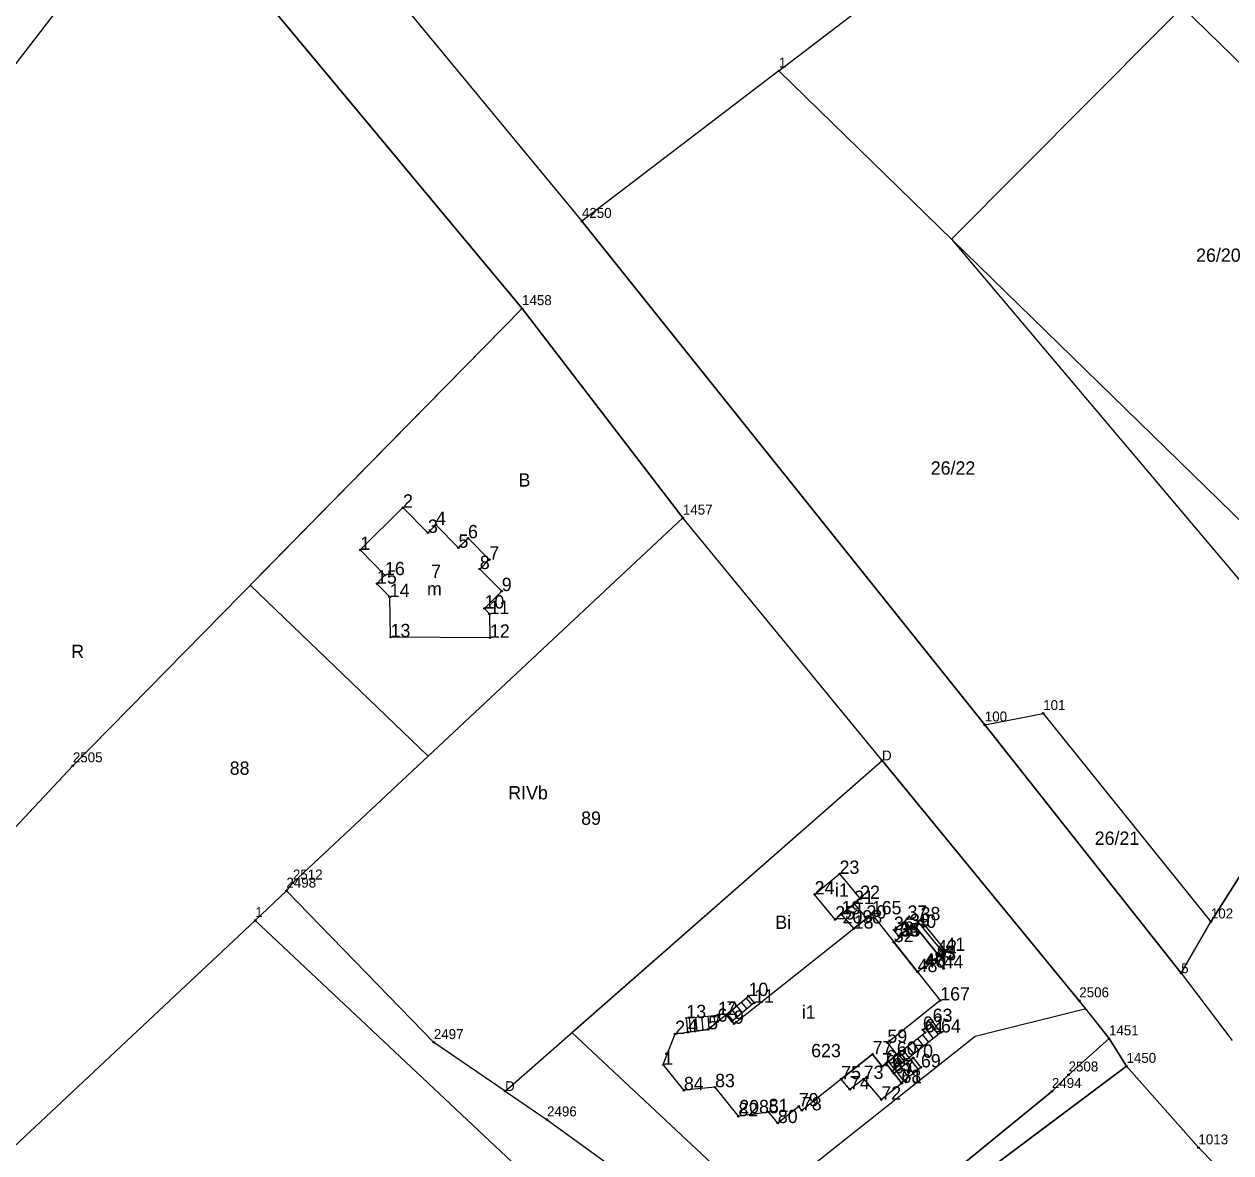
# Model space of a CAD drawing. Extents: x 7467189 to 7469366, y 5491487 to 5492734.
# Drawn here: x 7467609.4 to 7467745.4, y 5492014.5 to 5492141.7 of the extents above; entities that cross this region are included whole.
import ezdxf

# ---------------------------------------------------------------- set-up
doc = ezdxf.new("R2010")
doc.units = 0
for name, color, linetype in [('203-punkt graniczny', 7, 'Continuous'), ('203-punkt graniczny-Atr103', 7, 'Continuous'), ('209-oznaczenie konturu klasyfikacyjnego', 7, 'Continuous'), ('210-oznaczenie konturu użytku gruntowego', 7, 'Continuous'), ('211-numer działki ewidencyjnej', 7, 'Continuous'), ('217-kontur klasyfikacyjny', 7, 'Continuous'), ('218-kontur użytku gruntowego', 7, 'Continuous'), ('219-działka ewidencyjna', 7, 'Continuous'), ('312-budynek ewidencyjny', 7, 'Continuous'), ('312-oznaczenie budynku ewidencyjnego', 7, 'Continuous'), ('312-oznaczenie budynku ewidencyjnego-Atr117', 7, 'Continuous'), ('352-schody', 7, 'Continuous'), ('blok - nawis', 7, 'Continuous'), ('Punkt budynku', 7, 'Continuous'), ('Punkt budynku-Atr103', 7, 'Continuous'), ('Punkt budynku-Atr104', 7, 'Continuous')]:
    doc.layers.add(name, color=color, linetype=linetype)

# ---------------------------------------------------------------- blocks, each defined once
blk = doc.blocks.new('203')
blk.add_circle((0, 0), 0.09)
blk = doc.blocks.new('PUNKTBUD')
blk.add_circle((0, 0), 0.09)

msp = doc.modelspace()

# ---------------------------------------------------------------- linework, layer by layer
at = {"layer": '217-kontur klasyfikacyjny'}
for points in [[(7467768.85, 5492172.64), (7467713.9, 5492117.44)], [(7467665.5, 5492109.62), (7467624.48, 5492158.89)], [(7467651.98, 5492143.94), (7467672.25, 5492119.45)], [(7467672.25, 5492119.45), (7467717.66, 5492062.7)], [(7467713.9, 5492117.44), (7467758.45, 5492064.69)], [(7467634.87, 5492078.45), (7467665.5, 5492109.62)], [(7467683.63, 5492086.02), (7467654.93, 5492059.17)], [(7467706.08, 5492058.69), (7467683.63, 5492086.02)], [(7467654.93, 5492059.17), (7467634.87, 5492078.45)], [(7467743.14, 5492040.52), (7467758.45, 5492064.69)], [(7467717.66, 5492062.7), (7467739.8, 5492034.72)], [(7467671.13, 5492028.04), (7467706.08, 5492058.69)], [(7467739.8, 5492034.72), (7467743.14, 5492040.52)], [(7467728.94, 5492030.66), (7467716.58, 5492027.59)], [(7467729.04, 5492030.69), (7467728.94, 5492030.66)], [(7467731.66, 5492027.34), (7467729.04, 5492030.69)], [(7467692.22, 5492008.26), (7467671.13, 5492028.04)], [(7467716.58, 5492027.59), (7467692.22, 5492008.26)], [(7467727.1, 5492023.27), (7467731.66, 5492027.34)], [(7467733.63, 5492024.23), (7467703.66, 5492001.77)], [(7467741.74, 5492015.06), (7467733.63, 5492024.23)], [(7467725.22, 5492021.4), (7467727.1, 5492023.27)], [(7467711.49, 5492010.18), (7467725.22, 5492021.4)], [(7467745.33, 5492011.43), (7467741.74, 5492015.06)]]:
    msp.add_lwpolyline(points, dxfattribs=at)
at = {"layer": '218-kontur użytku gruntowego'}
for points in [[(7467665.5, 5492109.62), (7467624.48, 5492158.89)], [(7467651.98, 5492143.94), (7467672.25, 5492119.45)], [(7467672.25, 5492119.45), (7467717.66, 5492062.7)], [(7467665.5, 5492109.62), (7467634.87, 5492078.45)], [(7467683.63, 5492086.02), (7467665.5, 5492109.62)], [(7467654.93, 5492059.17), (7467683.63, 5492086.02)], [(7467706.08, 5492058.69), (7467683.63, 5492086.02)], [(7467634.87, 5492078.45), (7467654.93, 5492059.17)], [(7467743.14, 5492040.52), (7467758.45, 5492064.69)], [(7467717.66, 5492062.7), (7467739.8, 5492034.72)], [(7467671.13, 5492028.04), (7467706.08, 5492058.69)], [(7467728.31, 5492031.62), (7467706.08, 5492058.69)], [(7467739.8, 5492034.72), (7467743.14, 5492040.52)], [(7467729.04, 5492030.69), (7467728.31, 5492031.62)], [(7467728.94, 5492030.66), (7467716.58, 5492027.59)], [(7467729.04, 5492030.69), (7467728.94, 5492030.66)], [(7467731.66, 5492027.34), (7467729.04, 5492030.69)], [(7467692.22, 5492008.26), (7467671.13, 5492028.04)], [(7467716.58, 5492027.59), (7467692.22, 5492008.26)], [(7467731.66, 5492027.34), (7467727.1, 5492023.27)], [(7467733.63, 5492024.23), (7467731.66, 5492027.34)], [(7467711.14, 5492007.37), (7467733.63, 5492024.23)], [(7467741.74, 5492015.06), (7467733.63, 5492024.23)], [(7467727.1, 5492023.27), (7467725.22, 5492021.4)], [(7467725.22, 5492021.4), (7467711.49, 5492010.18)], [(7467745.33, 5492011.43), (7467741.74, 5492015.06)]]:
    msp.add_lwpolyline(points, dxfattribs=at)
at = {"layer": '219-działka ewidencyjna'}
for points in [[(7467624.48, 5492158.89), (7467665.5, 5492109.62)], [(7467694.46, 5492136.39), (7467724.09, 5492159.04)], [(7467724.09, 5492159.04), (7467782.84, 5492101.79)], [(7467613.61, 5492143.95), (7467605.35, 5492133.29)], [(7467651.98, 5492143.94), (7467672.25, 5492119.45)], [(7467694.46, 5492136.39), (7467672.25, 5492119.45)], [(7467694.46, 5492136.39), (7467762.1, 5492070.45)], [(7467717.66, 5492062.7), (7467672.25, 5492119.45)], [(7467614.87, 5492058.1), (7467665.5, 5492109.62)], [(7467665.5, 5492109.62), (7467683.63, 5492086.02)], [(7467639.67, 5492044.89), (7467683.63, 5492086.02)], [(7467706.08, 5492058.69), (7467683.63, 5492086.02)], [(7467762.1, 5492070.45), (7467743.14, 5492040.52)], [(7467717.66, 5492062.7), (7467724.24, 5492063.99)], [(7467724.24, 5492063.99), (7467743.14, 5492040.52)], [(7467739.8, 5492034.72), (7467717.66, 5492062.7)], [(7467598.43, 5492040.57), (7467614.87, 5492058.1)], [(7467663.59, 5492021.43), (7467706.08, 5492058.69)], [(7467706.08, 5492058.69), (7467728.31, 5492031.62)], [(7467638.94, 5492043.98), (7467639.67, 5492044.89)], [(7467635.43, 5492040.66), (7467638.94, 5492043.98)], [(7467638.94, 5492043.98), (7467655.56, 5492026.92)], [(7467605.73, 5492012.85), (7467635.43, 5492040.66)], [(7467635.43, 5492040.66), (7467685.71, 5491993.38)], [(7467739.8, 5492034.72), (7467743.14, 5492040.52)], [(7467739.8, 5492034.72), (7467745.55, 5492027.14)], [(7467728.31, 5492031.62), (7467731.66, 5492027.34)], [(7467663.59, 5492021.43), (7467655.56, 5492026.92)], [(7467727.1, 5492023.27), (7467731.66, 5492027.34)], [(7467731.66, 5492027.34), (7467733.63, 5492024.23)], [(7467703.66, 5492001.77), (7467733.63, 5492024.23)], [(7467733.63, 5492024.23), (7467741.74, 5492015.06)], [(7467725.22, 5492021.4), (7467727.1, 5492023.27)], [(7467663.59, 5492021.43), (7467668.32, 5492018.2)], [(7467711.49, 5492010.18), (7467725.22, 5492021.4)], [(7467668.32, 5492018.2), (7467694.32, 5491999.37)], [(7467741.74, 5492015.06), (7467745.33, 5492011.43)]]:
    msp.add_lwpolyline(points, dxfattribs=at)
at = {"layer": '312-budynek ewidencyjny'}
for points in [[(7467647.27, 5492082.42), (7467652.08, 5492087.18)], [(7467652.08, 5492087.18), (7467654.89, 5492084.34)], [(7467654.89, 5492084.34), (7467655.79, 5492085.23)], [(7467655.79, 5492085.23), (7467658.33, 5492082.66)], [(7467658.33, 5492082.66), (7467659.41, 5492083.73)], [(7467659.41, 5492083.73), (7467661.81, 5492081.32)], [(7467650.05, 5492079.57), (7467647.27, 5492082.42)], [(7467661.81, 5492081.32), (7467660.74, 5492080.26)], [(7467660.74, 5492080.26), (7467663.21, 5492077.78)], [(7467649.15, 5492078.61), (7467650.05, 5492079.57)], [(7467650.59, 5492077.11), (7467649.15, 5492078.61)], [(7467663.21, 5492077.78), (7467661.27, 5492075.81)], [(7467650.68, 5492072.58), (7467650.59, 5492077.11)], [(7467661.27, 5492075.81), (7467661.83, 5492075.2)], [(7467661.83, 5492075.2), (7467661.88, 5492072.52)], [(7467661.88, 5492072.52), (7467650.68, 5492072.58)], [(7467698.48, 5492043.59), (7467701.29, 5492045.91)], [(7467701.29, 5492045.91), (7467703.61, 5492043.09)], [(7467700.8, 5492040.77), (7467698.48, 5492043.59)], [(7467703.61, 5492043.09), (7467700.8, 5492040.77)], [(7467689.38, 5492029.02), (7467704.92, 5492041.35)], [(7467704.92, 5492041.35), (7467712.64, 5492031.64)], [(7467712.64, 5492031.64), (7467706.68, 5492026.87)], [(7467686.48, 5492028.39), (7467688.52, 5492030.05)], [(7467688.52, 5492030.05), (7467689.38, 5492029.02)], [(7467682.76, 5492027.87), (7467686.48, 5492028.39)], [(7467681.42, 5492024.41), (7467682.76, 5492027.87)], [(7467706.68, 5492026.87), (7467707.75, 5492025.52)], [(7467705.02, 5492025.58), (7467697.04, 5492019.26)], [(7467706.1, 5492024.21), (7467705.02, 5492025.58)], [(7467707.75, 5492025.52), (7467706.1, 5492024.21)], [(7467683.74, 5492021.53), (7467681.42, 5492024.41)], [(7467687.26, 5492021.87), (7467683.74, 5492021.53)], [(7467689.88, 5492018.6), (7467687.26, 5492021.87)], [(7467693.3, 5492019.06), (7467689.88, 5492018.6)], [(7467694.33, 5492017.83), (7467693.3, 5492019.06)], [(7467696.7, 5492019.71), (7467694.33, 5492017.83)], [(7467697.04, 5492019.26), (7467696.7, 5492019.71)]]:
    msp.add_lwpolyline(points, dxfattribs=at)
at = {"layer": '352-schody'}
for points in [[(7467708.09, 5492038.96), (7467707.98, 5492038.87), (7467707.42, 5492039.59), (7467708.95, 5492040.85), (7467710.42, 5492040.68), (7467713.23, 5492037.23), (7467713.01, 5492035.25), (7467712.21, 5492036.17), (7467712.29, 5492036.95), (7467709.95, 5492039.82), (7467709.23, 5492039.91)], [(7467708.09, 5492038.96), (7467707.98, 5492038.87), (7467707.42, 5492039.59), (7467708.95, 5492040.85), (7467710.42, 5492040.68), (7467713.23, 5492037.23), (7467713.01, 5492035.25), (7467712.21, 5492036.17), (7467712.29, 5492036.95), (7467709.95, 5492039.82), (7467709.23, 5492039.91)], [(7467707.4, 5492038.22), (7467708.18, 5492038.85), (7467708.09, 5492038.96), (7467709.23, 5492039.91), (7467709.95, 5492039.82), (7467712.29, 5492036.95), (7467712.21, 5492036.17), (7467712.08, 5492036.31), (7467710.96, 5492035.35), (7467710.87, 5492035.46), (7467710.09, 5492034.84)], [(7467707.4, 5492038.22), (7467708.18, 5492038.85), (7467708.09, 5492038.96), (7467709.23, 5492039.91), (7467709.95, 5492039.82), (7467712.29, 5492036.95), (7467712.21, 5492036.17), (7467712.08, 5492036.31), (7467710.96, 5492035.35), (7467710.87, 5492035.46), (7467710.09, 5492034.84)], [(7467688.52, 5492030.05), (7467691.02, 5492032.14), (7467691.66, 5492031.38), (7467689.16, 5492029.28)], [(7467688.52, 5492030.05), (7467691.02, 5492032.14), (7467691.66, 5492031.38), (7467689.16, 5492029.28)], [(7467684.19, 5492028.07), (7467684.02, 5492029.65), (7467687.57, 5492030), (7467687.53, 5492029.25), (7467686.48, 5492028.39)], [(7467684.19, 5492028.07), (7467684.02, 5492029.65), (7467687.57, 5492030), (7467687.53, 5492029.25), (7467686.48, 5492028.39)], [(7467707.23, 5492023.66), (7467706.53, 5492024.55), (7467707.75, 5492025.52), (7467710.92, 5492028.05), (7467710.68, 5492028.35), (7467711.78, 5492029.22), (7467712.72, 5492028.03)], [(7467707.23, 5492023.66), (7467706.53, 5492024.55), (7467707.75, 5492025.52), (7467710.92, 5492028.05), (7467710.68, 5492028.35), (7467711.78, 5492029.22), (7467712.72, 5492028.03)], [(7467708.27, 5492022.36), (7467707.41, 5492023.44), (7467709.59, 5492025.18), (7467710.46, 5492024.1)], [(7467708.27, 5492022.36), (7467707.41, 5492023.44), (7467709.59, 5492025.18), (7467710.46, 5492024.1)]]:
    msp.add_lwpolyline(points, close=True, dxfattribs=at)
for points in [[(7467709.92, 5492040.74), (7467713.18, 5492036.74)], [(7467689.68, 5492031.02), (7467690.32, 5492030.25)], [(7467690.21, 5492031.47), (7467690.85, 5492030.7)], [(7467690.75, 5492031.92), (7467691.39, 5492031.15)], [(7467684.52, 5492028.12), (7467684.37, 5492029.68)], [(7467685.22, 5492028.21), (7467685.07, 5492029.75)], [(7467685.91, 5492028.31), (7467685.76, 5492029.82)], [(7467686.6, 5492028.49), (7467686.46, 5492029.89)], [(7467687.25, 5492029.02), (7467687.16, 5492029.96)], [(7467688.6, 5492030.12), (7467689.25, 5492029.35)], [(7467689.14, 5492030.57), (7467689.78, 5492029.8)], [(7467711.89, 5492027.37), (7467710.94, 5492028.56)], [(7467712.43, 5492027.8), (7467711.49, 5492028.99)], [(7467710.24, 5492026.06), (7467709.54, 5492026.95)], [(7467710.79, 5492026.49), (7467710.08, 5492027.38)], [(7467711.34, 5492026.93), (7467710.63, 5492027.82)], [(7467708.6, 5492024.75), (7467707.89, 5492025.64)], [(7467709.15, 5492025.19), (7467708.44, 5492026.07)], [(7467709.7, 5492025.62), (7467708.99, 5492026.51)], [(7467707.5, 5492023.88), (7467706.8, 5492024.76)], [(7467708.05, 5492024.31), (7467707.35, 5492025.2)], [(7467709.09, 5492023.01), (7467708.23, 5492024.1)], [(7467709.64, 5492023.45), (7467708.78, 5492024.53)], [(7467710.19, 5492023.88), (7467709.33, 5492024.97)], [(7467708.54, 5492022.58), (7467707.69, 5492023.66)]]:
    msp.add_lwpolyline(points, dxfattribs=at)
at = {"layer": 'blok - nawis'}
for points in [[(7467702.89, 5492039.74), (7467701.51, 5492041.36), (7467702.92, 5492042.52), (7467704.32, 5492040.87)], [(7467701.47, 5492022.77), (7467705.02, 5492025.58), (7467706.1, 5492024.21), (7467706.53, 5492024.55), (7467707.23, 5492023.66), (7467707.41, 5492023.44), (7467708.27, 5492022.36), (7467708.32, 5492022.31), (7467706, 5492020.47), (7467704.01, 5492022.8), (7467702.45, 5492021.62)]]:
    msp.add_lwpolyline(points, close=True, dxfattribs=at)

# ---------------------------------------------------------------- block references
at = {"layer": '203-punkt graniczny'}
for p in [(7467694.46, 5492136.39), (7467672.25, 5492119.45), (7467665.5, 5492109.62), (7467683.63, 5492086.02), (7467724.24, 5492063.99), (7467717.66, 5492062.7), (7467614.87, 5492058.1), (7467706.08, 5492058.69), (7467639.67, 5492044.89), (7467638.94, 5492043.98), (7467635.43, 5492040.66), (7467743.14, 5492040.52), (7467739.8, 5492034.72), (7467728.31, 5492031.62), (7467655.56, 5492026.92), (7467731.66, 5492027.34), (7467733.63, 5492024.23), (7467727.1, 5492023.27), (7467663.59, 5492021.43), (7467725.22, 5492021.4), (7467668.32, 5492018.2), (7467741.74, 5492015.06)]:
    msp.add_blockref('203', p, dxfattribs=at)
at = {"layer": 'Punkt budynku'}
for p in [(7467652.08, 5492087.18), (7467655.79, 5492085.23), (7467654.89, 5492084.34), (7467658.33, 5492082.66), (7467659.41, 5492083.73), (7467647.27, 5492082.42), (7467661.81, 5492081.32), (7467660.74, 5492080.26), (7467649.15, 5492078.61), (7467650.05, 5492079.57), (7467650.59, 5492077.11), (7467663.21, 5492077.78), (7467661.27, 5492075.81), (7467661.83, 5492075.2), (7467650.68, 5492072.58), (7467661.88, 5492072.52), (7467701.29, 5492045.91), (7467698.48, 5492043.59), (7467703.61, 5492043.09), (7467702.92, 5492042.52), (7467700.8, 5492040.77), (7467701.51, 5492041.36), (7467704.32, 5492040.87), (7467704.92, 5492041.35), (7467708.95, 5492040.85), (7467710.42, 5492040.68), (7467702.89, 5492039.74), (7467707.42, 5492039.59), (7467708.09, 5492038.96), (7467709.23, 5492039.91), (7467709.95, 5492039.82), (7467707.4, 5492038.22), (7467707.98, 5492038.87), (7467708.18, 5492038.85), (7467712.08, 5492036.31), (7467712.29, 5492036.95), (7467713.23, 5492037.23), (7467710.87, 5492035.46), (7467710.96, 5492035.35), (7467712.21, 5492036.17), (7467713.01, 5492035.25), (7467710.09, 5492034.84), (7467691.02, 5492032.14), (7467691.66, 5492031.38), (7467712.64, 5492031.64), (7467684.02, 5492029.65), (7467687.57, 5492030), (7467688.52, 5492030.05), (7467684.19, 5492028.07), (7467686.48, 5492028.39), (7467687.53, 5492029.25), (7467689.16, 5492029.28), (7467689.38, 5492029.02), (7467710.68, 5492028.35), (7467711.78, 5492029.22), (7467682.76, 5492027.87), (7467706.68, 5492026.87), (7467710.92, 5492028.05), (7467712.72, 5492028.03), (7467705.02, 5492025.58), (7467707.75, 5492025.52), (7467681.42, 5492024.41), (7467706.1, 5492024.21), (7467706.53, 5492024.55), (7467709.59, 5492025.18), (7467710.46, 5492024.1), (7467701.47, 5492022.77), (7467704.01, 5492022.8), (7467707.23, 5492023.66), (7467707.41, 5492023.44), (7467683.74, 5492021.53), (7467687.26, 5492021.87), (7467702.45, 5492021.62), (7467708.27, 5492022.36), (7467708.32, 5492022.31), (7467706, 5492020.47), (7467689.88, 5492018.6), (7467693.3, 5492019.06), (7467696.7, 5492019.71), (7467697.04, 5492019.26), (7467694.33, 5492017.83)]:
    msp.add_blockref('PUNKTBUD', p, dxfattribs=at)

# ---------------------------------------------------------------- texts
at = {"layer": '203-punkt graniczny-Atr103'}
for s, height, p in [('1', 1.12, (7467694.46, 5492136.77)), ('4250', 1.125, (7467672.25, 5492119.83)), ('1458', 1.125, (7467665.5, 5492110)), ('1457', 1.125, (7467683.63, 5492086.39)), ('101', 1.125, (7467724.24, 5492064.37)), ('100', 1.125, (7467717.66, 5492063.08)), ('2505', 1.125, (7467614.87, 5492058.48)), ('D', 1.12, (7467706.08, 5492058.69)), ('2512', 1.125, (7467639.67, 5492045.27)), ('2498', 1.125, (7467638.94, 5492044.36)), ('1', 1.12, (7467635.43, 5492041.04)), ('102', 1.125, (7467743.14, 5492040.89)), ('5', 1.12, (7467739.8, 5492034.72)), ('2506', 1.125, (7467728.31, 5492032)), ('2497', 1.125, (7467655.56, 5492027.29)), ('1451', 1.125, (7467731.66, 5492027.71)), ('1450', 1.125, (7467733.63, 5492024.61)), ('2508', 1.125, (7467727.1, 5492023.64)), ('2494', 1.125, (7467725.22, 5492021.78)), ('D', 1.12, (7467663.59, 5492021.43)), ('2496', 1.125, (7467668.32, 5492018.58)), ('1013', 1.125, (7467741.74, 5492015.43))]:
    msp.add_text(s, height=height, dxfattribs=at).set_placement(p)
at = {"layer": '209-oznaczenie konturu klasyfikacyjnego'}
msp.add_text('RIVb', height=1.5, dxfattribs=at).set_placement((7467663.95, 5492054.3))
at = {"layer": '210-oznaczenie konturu użytku gruntowego'}
for s, p in [('B', (7467665.11, 5492089.55)), ('R', (7467614.68, 5492070.23)), ('Bi', (7467694.05, 5492039.71))]:
    msp.add_text(s, height=1.5, dxfattribs=at).set_placement(p)
at = {"layer": '211-numer działki ewidencyjnej'}
for s, p in [('26/20', (7467741.48, 5492114.88)), ('26/22', (7467711.57, 5492090.9)), ('88', (7467632.55, 5492057.08)), ('89', (7467672.16, 5492051.44)), ('26/21', (7467730.05, 5492049.18)), ('623', (7467698.09, 5492025.25))]:
    msp.add_text(s, height=1.5, dxfattribs=at).set_placement(p)
at = {"layer": '312-oznaczenie budynku ewidencyjnego'}
for s, p in [('7', (7467655.25, 5492079.25)), ('2098', (7467701.63, 5492040.33)), ('2085', (7467689.98, 5492018.93))]:
    msp.add_text(s, height=1.5, dxfattribs=at).set_placement(p)
at = {"layer": '312-oznaczenie budynku ewidencyjnego-Atr117'}
for s, p in [('m', (7467654.79, 5492077.28)), ('i1', (7467700.76, 5492043.33)), ('i1', (7467697.03, 5492029.59))]:
    msp.add_text(s, height=1.5, dxfattribs=at).set_placement(p)
at = {"layer": 'Punkt budynku-Atr103'}
for s, p in [('23', (7467701.29, 5492045.91)), ('24', (7467698.48, 5492043.59)), ('22', (7467703.61, 5492043.09)), ('25', (7467700.8, 5492040.77)), ('165', (7467704.92, 5492041.35)), ('167', (7467712.64, 5492031.64)), ('7', (7467688.52, 5492030.05)), ('5', (7467686.48, 5492028.39)), ('9', (7467689.38, 5492029.02)), ('2', (7467682.76, 5492027.87)), ('59', (7467706.68, 5492026.87)), ('77', (7467705.02, 5492025.58)), ('60', (7467707.75, 5492025.52)), ('1', (7467681.42, 5492024.41)), ('76', (7467706.1, 5492024.21)), ('84', (7467683.74, 5492021.53)), ('83', (7467687.26, 5492021.87)), ('82', (7467689.88, 5492018.6)), ('81', (7467693.3, 5492019.06)), ('79', (7467696.7, 5492019.71)), ('78', (7467697.04, 5492019.26)), ('80', (7467694.33, 5492017.83))]:
    msp.add_text(s, height=1.5, dxfattribs=at).set_placement(p)
at = {"layer": 'Punkt budynku-Atr104'}
for s, p in [('2', (7467652.08, 5492087.18)), ('4', (7467655.79, 5492085.23)), ('3', (7467654.89, 5492084.34)), ('5', (7467658.33, 5492082.66)), ('6', (7467659.41, 5492083.73)), ('1', (7467647.27, 5492082.42)), ('7', (7467661.81, 5492081.32)), ('8', (7467660.74, 5492080.26)), ('15', (7467649.15, 5492078.61)), ('16', (7467650.05, 5492079.57)), ('14', (7467650.59, 5492077.11)), ('9', (7467663.21, 5492077.78)), ('10', (7467661.27, 5492075.81)), ('11', (7467661.83, 5492075.2)), ('13', (7467650.68, 5492072.58)), ('12', (7467661.88, 5492072.52)), ('21', (7467702.92, 5492042.52)), ('19', (7467701.51, 5492041.36)), ('20', (7467704.32, 5492040.87)), ('37', (7467708.95, 5492040.85)), ('38', (7467710.42, 5492040.68)), ('18', (7467702.89, 5492039.74)), ('36', (7467707.42, 5492039.59)), ('34', (7467708.09, 5492038.96)), ('39', (7467709.23, 5492039.91)), ('40', (7467709.95, 5492039.82)), ('32', (7467707.4, 5492038.22)), ('33', (7467707.98, 5492038.87)), ('35', (7467708.18, 5492038.85)), ('45', (7467712.08, 5492036.31)), ('43', (7467712.21, 5492036.17)), ('42', (7467712.29, 5492036.95)), ('41', (7467713.23, 5492037.23)), ('48', (7467710.09, 5492034.84)), ('47', (7467710.87, 5492035.46)), ('46', (7467710.96, 5492035.35)), ('44', (7467713.01, 5492035.25)), ('10', (7467691.02, 5492032.14)), ('11', (7467691.66, 5492031.38)), ('13', (7467684.02, 5492029.65)), ('12', (7467687.57, 5492030)), ('4', (7467684.19, 5492028.07)), ('6', (7467687.53, 5492029.25)), ('62', (7467710.68, 5492028.35)), ('61', (7467710.92, 5492028.05)), ('63', (7467711.78, 5492029.22)), ('64', (7467712.72, 5492028.03)), ('66', (7467706.53, 5492024.55)), ('70', (7467709.59, 5492025.18)), ('69', (7467710.46, 5492024.1)), ('75', (7467701.47, 5492022.77)), ('73', (7467704.01, 5492022.8)), ('65', (7467707.23, 5492023.66)), ('67', (7467707.41, 5492023.44)), ('74', (7467702.45, 5492021.62)), ('68', (7467708.27, 5492022.36)), ('71', (7467708.32, 5492022.31)), ('72', (7467706, 5492020.47))]:
    msp.add_text(s, height=1.5, dxfattribs=at).set_placement(p)

doc.saveas('drawing.dxf')
